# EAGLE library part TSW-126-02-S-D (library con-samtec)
THROUGH-HOLE .025" SQ POST HEADER Source: Samtec TSW.pdf
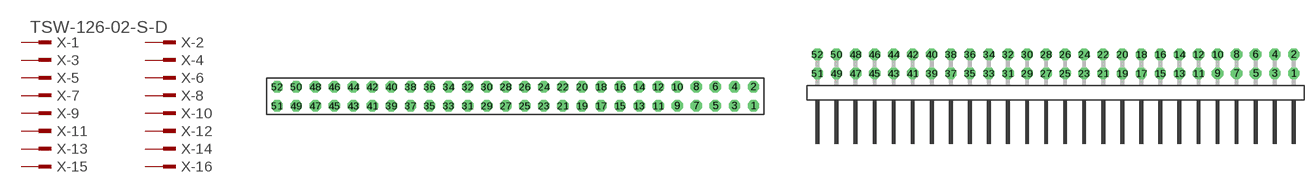
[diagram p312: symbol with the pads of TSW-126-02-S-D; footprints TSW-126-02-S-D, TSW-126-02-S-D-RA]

Designator prefix X; gates -1=MPINV -2=MPIN -3=MPIN -4=MPIN -5=MPIN -6=MPIN -7=MPIN -8=MPIN -9=MPIN -10=MPIN -11=MPIN -12=MPIN -13=MPIN -14=MPIN -15=MPIN -16=MPIN -17=MPIN -18=MPIN -19=MPIN -20=MPIN -21=MPIN -22=MPIN -23=MPIN -24=MPIN -25=MPIN -26=MPIN -27=MPIN -28=MPIN -29=MPIN -30=MPIN -31=MPIN -32=MPIN -33=MPIN -34=MPIN -35=MPIN -36=MPIN -37=MPIN -38=MPIN -39=MPIN -40=MPIN -41=MPIN -42=MPIN -43=MPIN -44=MPIN -45=MPIN -46=MPIN -47=MPIN -48=MPIN -49=MPIN -50=MPIN -51=MPIN -52=MPIN

## TSW-126-02-S-D (OC_FARNELL: unknown; OC_NEWARK: unknown)  [TSW-126-02-S-D]
1  -1:1  pas
2  -2:1  pas
3  -3:1  pas
4  -4:1  pas
5  -5:1  pas
6  -6:1  pas
7  -7:1  pas
8  -8:1  pas
9  -9:1  pas
10  -10:1  pas
11  -11:1  pas
12  -12:1  pas
13  -13:1  pas
14  -14:1  pas
15  -15:1  pas
16  -16:1  pas
17  -17:1  pas
18  -18:1  pas
19  -19:1  pas
20  -20:1  pas
21  -21:1  pas
22  -22:1  pas
23  -23:1  pas
24  -24:1  pas
25  -25:1  pas
26  -26:1  pas
27  -27:1  pas
28  -28:1  pas
29  -29:1  pas
30  -30:1  pas
31  -31:1  pas
32  -32:1  pas
33  -33:1  pas
34  -34:1  pas
35  -35:1  pas
36  -36:1  pas
37  -37:1  pas
38  -38:1  pas
39  -39:1  pas
40  -40:1  pas
41  -41:1  pas
42  -42:1  pas
43  -43:1  pas
44  -44:1  pas
45  -45:1  pas
46  -46:1  pas
47  -47:1  pas
48  -48:1  pas
49  -49:1  pas
50  -50:1  pas
51  -51:1  pas
52  -52:1  pas

## TSW-126-02-S-D-RA (OC_FARNELL: unknown; OC_NEWARK: unknown)  [TSW-126-02-S-D-RA]
Pads as for TSW-126-02-S-D

## Footprint TSW-126-02-S-D (pad centres in mm)
THROUGH-HOLE .025" SQ POST HEADER Source: Samtec TSW.pdf
drill 1 pad 1.5 octagon: 1 31.75,-1.27; 2 31.75,1.27; 3 29.21,-1.27; 4 29.21,1.27; 5 26.67,-1.27; 6 26.67,1.27; 7 24.13,-1.27; 8 24.13,1.27; 9 21.59,-1.27; 10 21.59,1.27; 11 19.05,-1.27; 12 19.05,1.27; 13 16.51,-1.27; 14 16.51,1.27; 15 13.97,-1.27; 16 13.97,1.27; 17 11.43,-1.27; 18 11.43,1.27; 19 8.89,-1.27; 20 8.89,1.27; 21 6.35,-1.27; 22 6.35,1.27; 23 3.81,-1.27; 24 3.81,1.27; 25 1.27,-1.27; 26 1.27,1.27; 27 -1.27,-1.27; 28 -1.27,1.27; 29 -3.81,-1.27; 30 -3.81,1.27; 31 -6.35,-1.27; 32 -6.35,1.27; 33 -8.89,-1.27; 34 -8.89,1.27; 35 -11.43,-1.27; 36 -11.43,1.27; 37 -13.97,-1.27; 38 -13.97,1.27; 39 -16.51,-1.27; 40 -16.51,1.27; 41 -19.05,-1.27; 42 -19.05,1.27; 43 -21.59,-1.27; 44 -21.59,1.27; 45 -24.13,-1.27; 46 -24.13,1.27; 47 -26.67,-1.27; 48 -26.67,1.27; 49 -29.21,-1.27; 50 -29.21,1.27; 51 -31.75,-1.27; 52 -31.75,1.27

## Footprint TSW-126-02-S-D-RA (pad centres in mm)
THROUGH-HOLE .025" SQ POST HEADER Source: Samtec TSW.pdf
drill 1 pad 1.5 octagon: 1 31.75,1.524; 2 31.75,4.064; 3 29.21,1.524; 4 29.21,4.064; 5 26.67,1.524; 6 26.67,4.064; 7 24.13,1.524; 8 24.13,4.064; 9 21.59,1.524; 10 21.59,4.064; 11 19.05,1.524; 12 19.05,4.064; 13 16.51,1.524; 14 16.51,4.064; 15 13.97,1.524; 16 13.97,4.064; 17 11.43,1.524; 18 11.43,4.064; 19 8.89,1.524; 20 8.89,4.064; 21 6.35,1.524; 22 6.35,4.064; 23 3.81,1.524; 24 3.81,4.064; 25 1.27,1.524; 26 1.27,4.064; 27 -1.27,1.524; 28 -1.27,4.064; 29 -3.81,1.524; 30 -3.81,4.064; 31 -6.35,1.524; 32 -6.35,4.064; 33 -8.89,1.524; 34 -8.89,4.064; 35 -11.43,1.524; 36 -11.43,4.064; 37 -13.97,1.524; 38 -13.97,4.064; 39 -16.51,1.524; 40 -16.51,4.064; 41 -19.05,1.524; 42 -19.05,4.064; 43 -21.59,1.524; 44 -21.59,4.064; 45 -24.13,1.524; 46 -24.13,4.064; 47 -26.67,1.524; 48 -26.67,4.064; 49 -29.21,1.524; 50 -29.21,4.064; 51 -31.75,1.524; 52 -31.75,4.064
